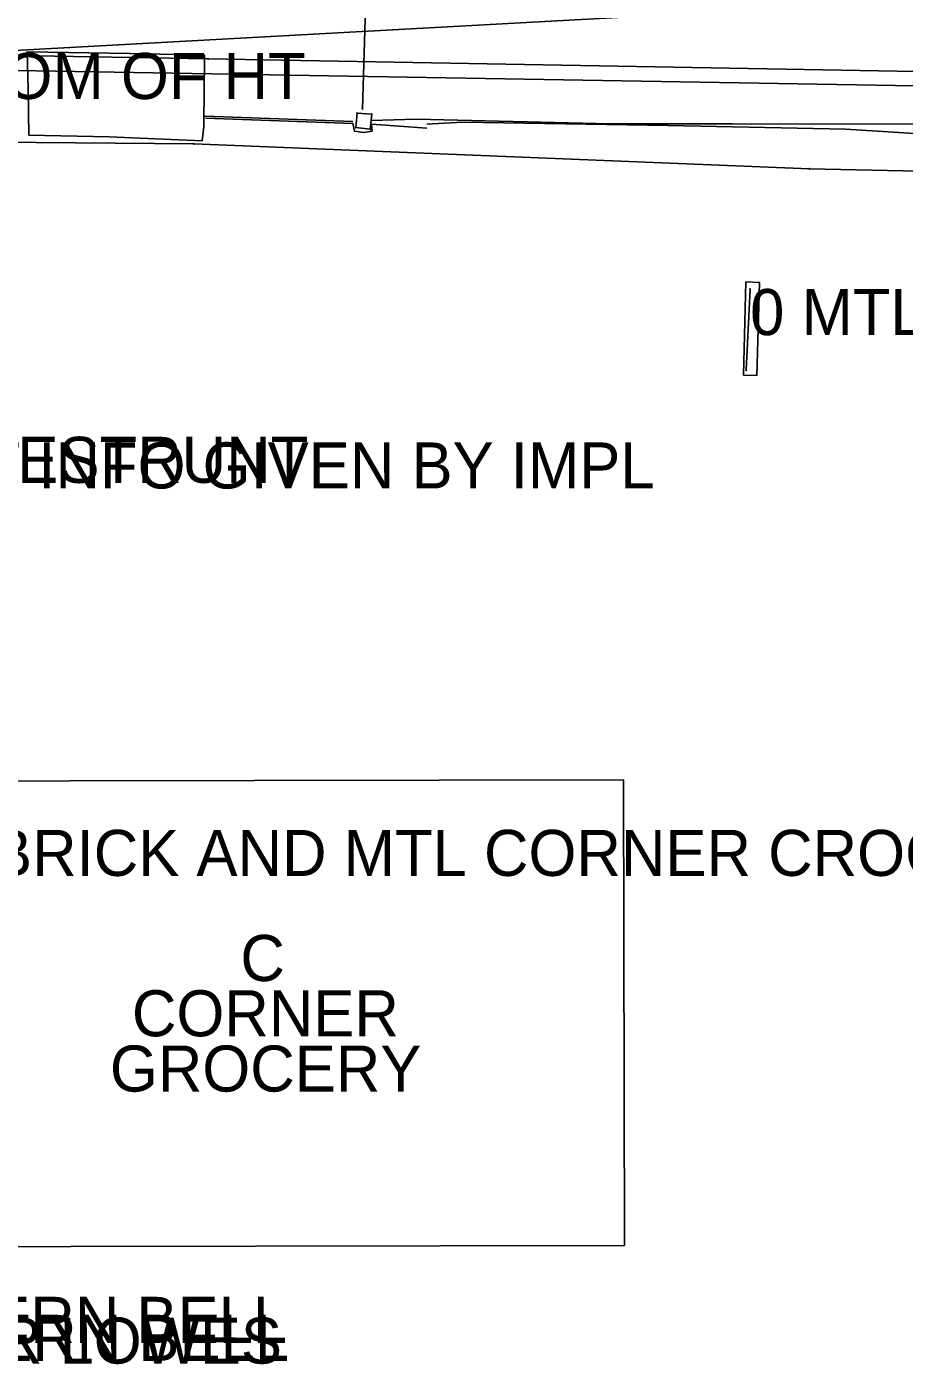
# Model space of a CAD drawing. Extents: x 1304270 to 1306561, y 1876019 to 1876752.
# Drawn here: x 1305040.8 to 1305136, y 1876258.5 to 1876403.7 of the extents above; entities that cross this region are included whole.
import ezdxf

# ---------------------------------------------------------------- set-up
doc = ezdxf.new("R2010")
doc.units = 0
for name, color, linetype in [('Default', 7, 'Continuous'), ('S_BUILDING', 7, 'Continuous'), ('S_BUILDING_ANNOT', 7, 'Continuous'), ('S_DRG_PT_SYM', 7, 'Continuous'), ('S_DROP_INLET', 7, 'Continuous'), ('S_EDGE_CONCRETE', 7, 'Continuous'), ('S_EDGE_PAVEMENT', 7, 'Continuous'), ('S_ELECTRIC_UTILITIES_ANNOT', 7, 'Continuous'), ('S_FIBER_OPTIC_CABLE', 7, 'Continuous'), ('S_GAS_UTILITIES', 7, 'Continuous'), ('S_MANHOLE_ANNOT', 7, 'Continuous'), ('S_MSC_PT_SYM', 7, 'Continuous'), ('S_SIGN', 7, 'Continuous'), ('S_SIGN_ANNOT', 7, 'Continuous'), ('S_TELEPHONE_UTILITIES_ANNOT', 7, 'Continuous'), ('S_UTL_PT_SYM', 7, 'Continuous'), ('S_WATER_UTILITIES', 7, 'Continuous'), ('S_WATER_UTILITIES_ANNOT', 7, 'Continuous')]:
    doc.layers.add(name, color=color, linetype=linetype)

msp = doc.modelspace()

# ---------------------------------------------------------------- linework, layer by layer
at = {"layer": 'Default'}
msp.add_line((1304873.94, 1876392.06), (1305473.53, 1876424.94), dxfattribs=at)
at = {"layer": 'S_BUILDING'}
msp.add_lwpolyline([(1305105.68, 1876271.43), (1305025.53, 1876271.29), (1305025.44, 1876321.83), (1305105.6, 1876321.96)], close=True, dxfattribs=at)
at = {"layer": 'S_DRG_PT_SYM'}
for points in [[(1305076.68, 1876394.36), (1305076.68, 1876394.41), (1305076.68, 1876394.36), (1305076.63, 1876394.36), (1305076.68, 1876394.36), (1305076.68, 1876394.31), (1305076.68, 1876394.36), (1305076.73, 1876394.36)], [(1305078.26, 1876394.24), (1305078.26, 1876394.29), (1305078.26, 1876394.24), (1305078.21, 1876394.24), (1305078.26, 1876394.24), (1305078.26, 1876394.19), (1305078.26, 1876394.24), (1305078.31, 1876394.24)], [(1305076.53, 1876392.78), (1305076.53, 1876392.83), (1305076.53, 1876392.78), (1305076.48, 1876392.78), (1305076.53, 1876392.78), (1305076.53, 1876392.73), (1305076.53, 1876392.78), (1305076.58, 1876392.78)], [(1305078.11, 1876392.62), (1305078.11, 1876392.67), (1305078.11, 1876392.62), (1305078.06, 1876392.62), (1305078.11, 1876392.62), (1305078.11, 1876392.57), (1305078.11, 1876392.62), (1305078.16, 1876392.62)]]:
    msp.add_lwpolyline(points, dxfattribs=at)
at = {"layer": 'S_DROP_INLET'}
for p, q in [((1305076.68, 1876394.36), (1305076.53, 1876392.78)), ((1305078.26, 1876394.24), (1305076.68, 1876394.36)), ((1305078.11, 1876392.62), (1305078.26, 1876394.24)), ((1305076.53, 1876392.78), (1305078.11, 1876392.62))]:
    msp.add_line(p, q, dxfattribs=at)
at = {"layer": 'S_EDGE_CONCRETE'}
for points in [[(1305041.07, 1876391.95), (1305040.98, 1876396.96), (1305040.88, 1876401.01), (1305052.05, 1876400.83), (1305060.13, 1876400.64), (1305060.08, 1876396.27), (1305060.03, 1876393.82), (1305060.05, 1876392.89), (1305059.86, 1876391.35), (1305049.76, 1876391.79)], [(1305118.61, 1876365.9), (1305120.04, 1876365.85), (1305120.33, 1876375.95), (1305118.86, 1876376.03)]]:
    msp.add_lwpolyline(points, close=True, dxfattribs=at)
at = {"layer": 'S_EDGE_PAVEMENT'}
for points in [[(1305076.2, 1876393.44), (1305060.15, 1876394.03)], [(1305060.22, 1876393.81), (1305076.22, 1876393.24), (1305076.38, 1876392.38), (1305077.39, 1876392.23), (1305078.3, 1876392.4), (1305078.25, 1876393.16), (1305084.24, 1876392.73)], [(1305078.23, 1876393.56), (1305083.08, 1876393.71)], [(1305083.08, 1876393.71), (1305104.14, 1876393.18), (1305117.43, 1876393.17), (1305130.73, 1876393.16), (1305148.24, 1876393.22), (1305165.75, 1876393.28)], [(1305193.68, 1876353.97), (1305193.6, 1876366.51), (1305193.52, 1876379.04), (1305193.25, 1876389.96), (1305192.97, 1876390.22), (1305192.38, 1876390.91), (1305188.76, 1876391.64), (1305184.02, 1876391.89), (1305180.63, 1876391.66), (1305178.22, 1876391.48), (1305178.06, 1876390.92), (1305172.3, 1876391.03), (1305171.77, 1876391.06), (1305170.06, 1876391.08), (1305168.86, 1876391.09), (1305166.22, 1876391.34), (1305156.83, 1876391.81), (1305139.46, 1876391.99), (1305129.66, 1876392.59), (1305110.42, 1876393.02), (1305088.15, 1876393.37), (1305086.11, 1876393.25), (1305084.26, 1876393.15)]]:
    msp.add_lwpolyline(points, dxfattribs=at)
at = {"layer": 'S_FIBER_OPTIC_CABLE'}
for p, q in [((1305060.48, 1876400.23), (1305022.32, 1876400.93)), ((1305352.56, 1876393.61), (1305019.82, 1876399.32)), ((1305152.63, 1876398.59), (1305060.48, 1876400.23))]:
    msp.add_line(p, q, dxfattribs=at)
at = {"layer": 'S_GAS_UTILITIES'}
for p, q in [((1305058.95, 1876391.01), (1305006.09, 1876391.43)), ((1305125.76, 1876388.29), (1305058.95, 1876391.01)), ((1305150.7, 1876387.79), (1305125.76, 1876388.29))]:
    msp.add_line(p, q, dxfattribs=at)
at = {"layer": 'S_MSC_PT_SYM'}
for points in [[(1305119.32, 1876375.25), (1305119.32, 1876375.3), (1305119.32, 1876375.25), (1305119.27, 1876375.25), (1305119.32, 1876375.25), (1305119.32, 1876375.2), (1305119.32, 1876375.25), (1305119.37, 1876375.25)], [(1305118.9, 1876366.43), (1305118.9, 1876366.48), (1305118.9, 1876366.43), (1305118.85, 1876366.43), (1305118.9, 1876366.43), (1305118.9, 1876366.38), (1305118.9, 1876366.43), (1305118.95, 1876366.43)]]:
    msp.add_lwpolyline(points, dxfattribs=at)
at = {"layer": 'S_SIGN'}
msp.add_line((1305119.32, 1876375.25), (1305118.9, 1876366.43), dxfattribs=at)
at = {"layer": 'S_UTL_PT_SYM'}
for points in [[(1305060.48, 1876400.23), (1305060.48, 1876400.28), (1305060.48, 1876400.23), (1305060.43, 1876400.23), (1305060.48, 1876400.23), (1305060.48, 1876400.18), (1305060.48, 1876400.23), (1305060.53, 1876400.23)], [(1305077.27, 1876394.82), (1305077.27, 1876394.87), (1305077.27, 1876394.82), (1305077.22, 1876394.82), (1305077.27, 1876394.82), (1305077.27, 1876394.77), (1305077.27, 1876394.82), (1305077.32, 1876394.82)], [(1305058.95, 1876391.01), (1305058.95, 1876391.06), (1305058.95, 1876391.01), (1305058.9, 1876391.01), (1305058.95, 1876391.01), (1305058.95, 1876390.96), (1305058.95, 1876391.01), (1305059, 1876391.01)], [(1305125.76, 1876388.29), (1305125.76, 1876388.34), (1305125.76, 1876388.29), (1305125.71, 1876388.29), (1305125.76, 1876388.29), (1305125.76, 1876388.24), (1305125.76, 1876388.29), (1305125.81, 1876388.29)]]:
    msp.add_lwpolyline(points, dxfattribs=at)
at = {"layer": 'S_WATER_UTILITIES'}
msp.add_line((1305077.27, 1876394.82), (1305078.04, 1876421.15), dxfattribs=at)

# ---------------------------------------------------------------- texts
at = {"layer": 'S_BUILDING_ANNOT'}
for s, p in [('1 STRY BRICK ABNDON RESTR RESTRUNT', (1304932.44, 1876354.21)), ('BRICK AND MTL CORNER CROCERY AND MRKT', (1305036.95, 1876311.54)), ('C', (1305064.01, 1876300.13)), ('CORNER', (1305052.24, 1876294.13)), ('GROCERY', (1305049.85, 1876288.13))]:
    msp.add_text(s, height=5, dxfattribs=at).set_placement(p)
at = {"layer": 'S_ELECTRIC_UTILITIES_ANNOT'}
msp.add_text('POINT ON ROAD UNDER LOWES', height=5, dxfattribs=at).set_placement((1304963.4, 1876258.6))
at = {"layer": 'S_MANHOLE_ANNOT'}
msp.add_text('BOTTOM OF HT', height=5, dxfattribs=at).set_placement((1305020.59, 1876395.88))
at = {"layer": 'S_SIGN_ANNOT'}
msp.add_text('0 MTL MTL CONC BASE NONE', height=5, dxfattribs=at).set_placement((1305119.32, 1876370.25))
at = {"layer": 'S_TELEPHONE_UTILITIES_ANNOT'}
for p in [(1304994.04, 1876260.85), (1304994.25, 1876258.9)]:
    msp.add_text('SOUTHWESTERN BELL', height=5, dxfattribs=at).set_placement(p)
at = {"layer": 'S_WATER_UTILITIES_ANNOT'}
msp.add_text('DIRECTION OF INFO GIVEN BY IMPL', height=5, dxfattribs=at).set_placement((1304992.31, 1876353.6))

doc.saveas('drawing.dxf')
